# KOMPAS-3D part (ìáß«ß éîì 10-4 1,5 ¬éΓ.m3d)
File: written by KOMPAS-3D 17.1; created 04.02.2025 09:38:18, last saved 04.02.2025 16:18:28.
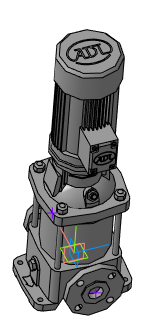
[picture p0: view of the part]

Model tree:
1. Точка:3
     X = 140; Координата X = 140
2. Точка:4
     X = -140; Координата X = -140
3. Операция без истории:2  (labels: Насос ВМН 10-4 1,5 кВт)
